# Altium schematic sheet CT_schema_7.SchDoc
size 278 x 170 mm
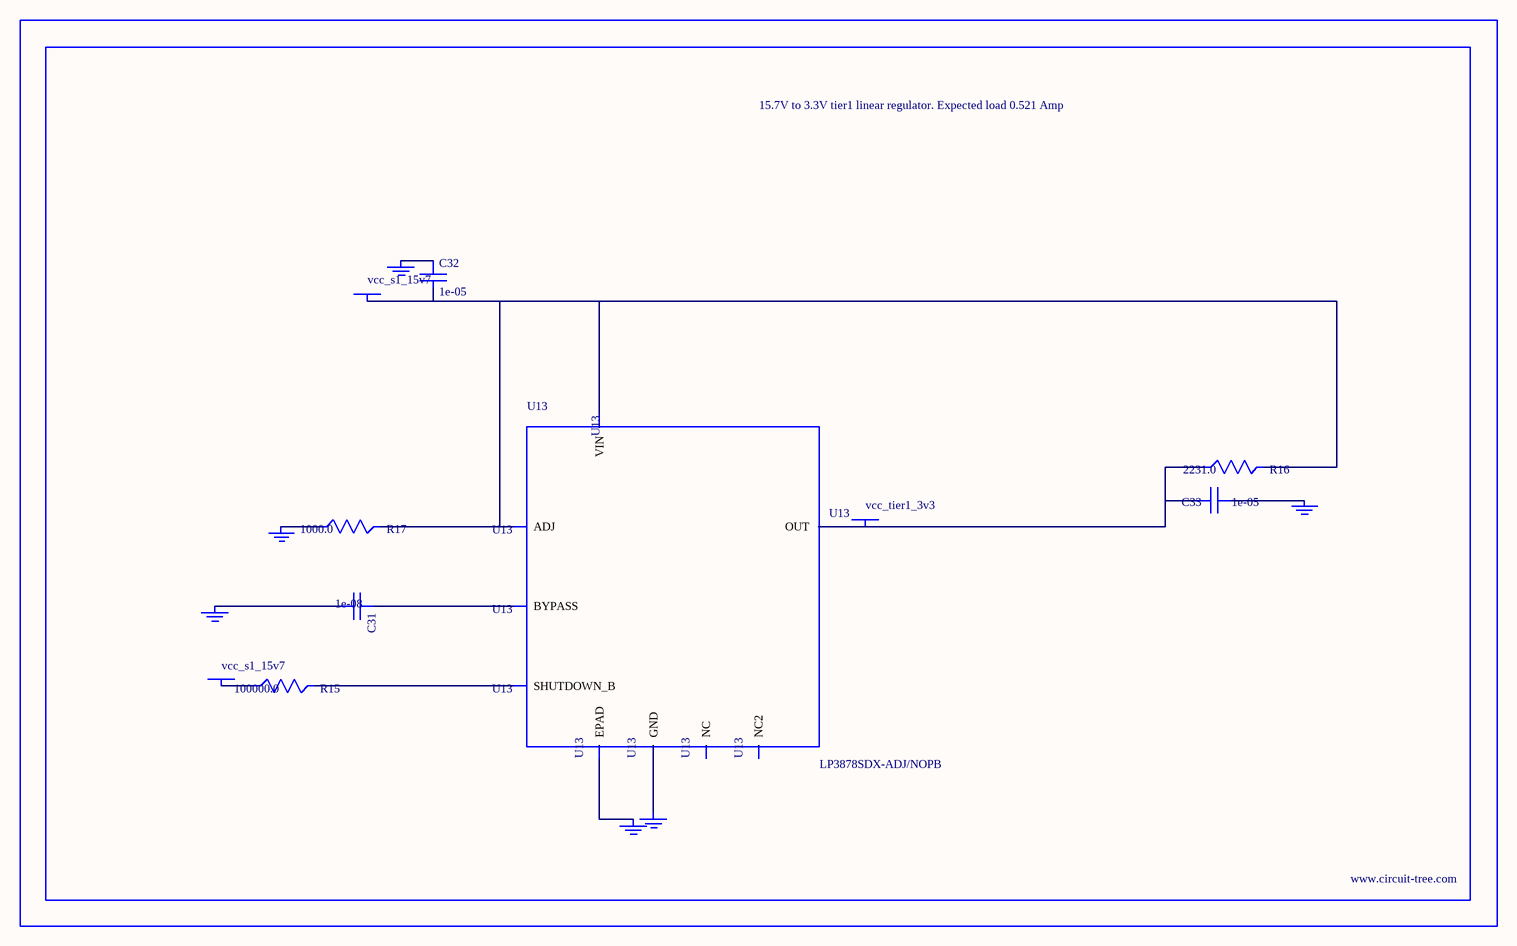
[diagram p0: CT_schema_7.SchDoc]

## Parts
BORDER6  (no value)
C31  1e-08  [C0402]
C32  1e-05  [C1210]
C33  1e-05  [C1210]
GND_INSTANCE_6_0  (no value)
GND_INSTANCE_6_1  (no value)
GND_INSTANCE_6_2  (no value)
GND_INSTANCE_6_3  (no value)
GND_INSTANCE_6_4  (no value)
GND_INSTANCE_6_5  (no value)
POWER_INSTANCE_6_0  vcc_s1_15v7
POWER_INSTANCE_6_1  vcc_s1_15v7
POWER_INSTANCE_6_2  vcc_tier1_3v3
R15  100000.0  [R0603]
R16  2231.0  [R0603]
R17  1000.0  [R0603]
U13  LP3878SDX-ADJ/NOPB  [WSON-8]

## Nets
NetC31_1: C31.1 U13.1(BYPASS)
NetC31_2: C31.2 GND_INSTANCE_6_0.0(GND)
NetC32_1: C32.1 GND_INSTANCE_6_1.0(GND)
NetC32_2: C32.2 POWER_INSTANCE_6_0.0(PWR) R16.2 R17.2 U13.4(VIN) U13.6(ADJ)
NetC33_1: C33.1 GND_INSTANCE_6_2.0(GND)
NetC33_2: C33.2 POWER_INSTANCE_6_2.0(PWR) R16.1 U13.5(OUT)
NetGND_INSTANCE_6_3_0: GND_INSTANCE_6_3.0(GND) R17.1
NetGND_INSTANCE_6_4_0: GND_INSTANCE_6_4.0(GND) U13.PAD(EPAD)
NetGND_INSTANCE_6_5_0: GND_INSTANCE_6_5.0(GND) U13.3(GND)
NetPOWER_INSTANCE_6_1_0: POWER_INSTANCE_6_1.0(PWR) R15.1
NetR15_2: R15.2 U13.8(SHUTDOWN_B)

Not connected (* = marked no-connect by the designer): U13 2(NC) 7(NC2)

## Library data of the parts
BORDER6 = BORDER_PAGE6
C31 = C0402C103K3RAC
C32 = C1210C106K5PACTU
C33 = GRM32DR61E106MA12L
GND_INSTANCE_6_0-GND_INSTANCE_6_5 = GND
POWER_INSTANCE_6_0-POWER_INSTANCE_6_2 = PWR
R15 = RC0603JR-07100KL
R16 = R16
R17 = RC0603JR-071KL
